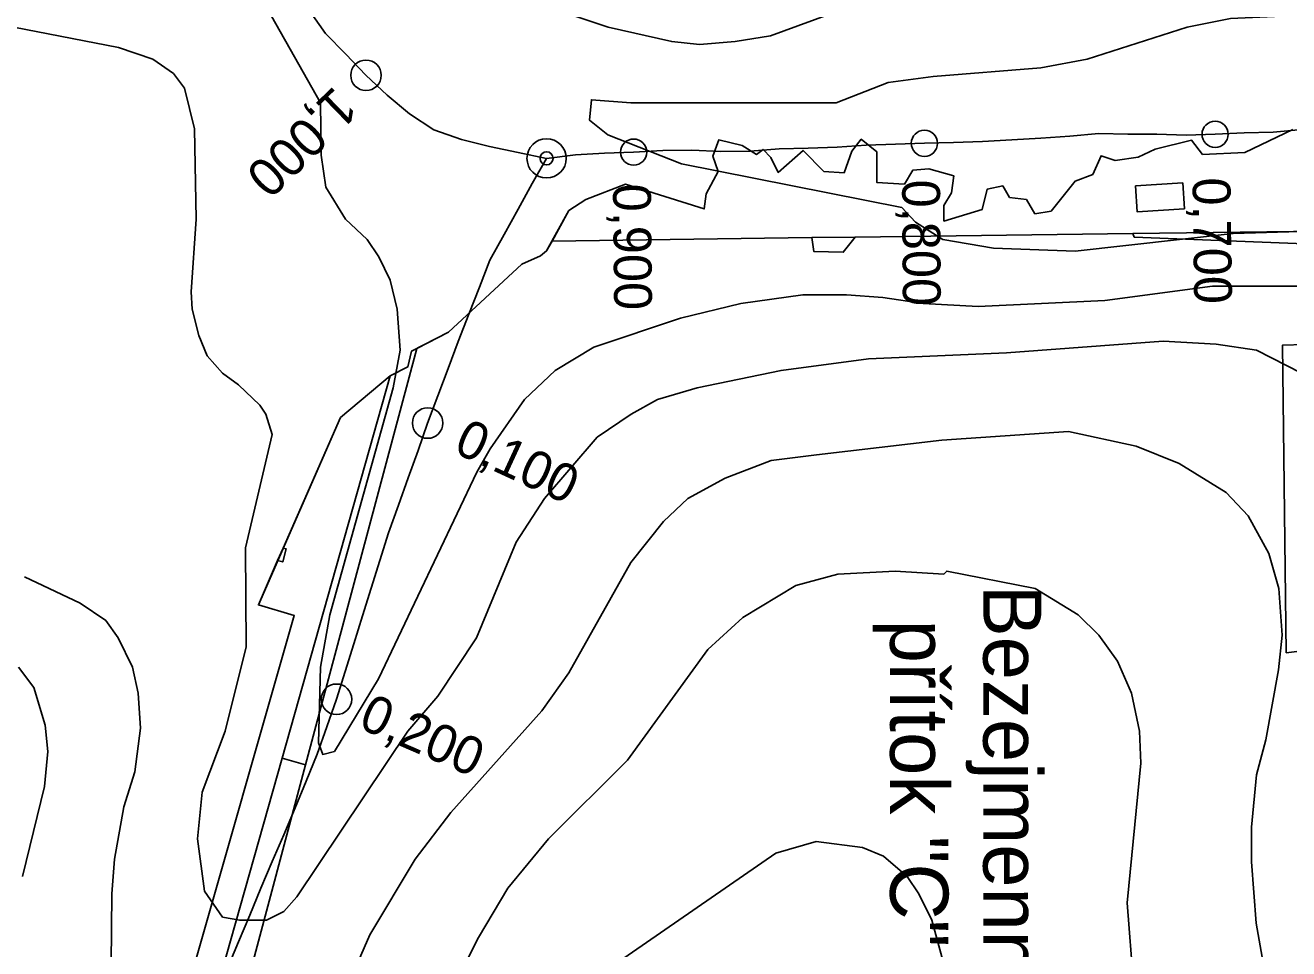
# Model space of a CAD drawing. Extents: x -510989 to -501240, y -1184665 to -1176098.
# Drawn here: x -505664.2 to -505230.1, y -1181158.8 to -1180841.4 of the extents above; entities that cross this region are included whole.
import ezdxf

# ---------------------------------------------------------------- set-up
doc = ezdxf.new("R2010")
doc.units = 0
for name, color, linetype in [('lesni_pozemek', 7, 'Continuous'), ('NAVRH_rozvodnice', 7, 'Continuous'), ('ostatni_plocha_x_jina_plocha', 7, 'Continuous'), ('ostatni_plocha_x_manipulacni_plocha', 7, 'Continuous'), ('popis', 7, 'Continuous'), ('trasovani_toku', 7, 'Continuous'), ('vrstevnice_01', 7, 'Continuous'), ('vrstevnice_02', 7, 'Continuous'), ('zahrada', 7, 'Continuous'), ('zastavena_plocha_a_nadvori', 7, 'Continuous')]:
    doc.layers.add(name, color=color, linetype=linetype)

msp = doc.modelspace()

# ---------------------------------------------------------------- linework, layer by layer
at = {"layer": 'lesni_pozemek'}
for points in [[(-505674.96, -1181355.48), (-505644.72, -1181306.04), (-505608, -1181246), (-505567.89, -1181095.59), (-505529.72, -1180952.45), (-505518.81, -1180946.9), (-505493.6, -1180923.5), (-505487.17, -1180920.65), (-505485.1, -1180918.93), (-505483.22, -1180915.53), (-505393.95, -1180914.37), (-505393.27, -1180919.16), (-505383.14, -1180919.37), (-505379.08, -1180914.18), (-505283.65, -1180912.95), (-505283.21, -1180914.2), (-505209.9, -1180917.09)], [(-505209.22, -1180950.61), (-505232.2, -1180951.3), (-505230.99, -1181057.06), (-505207.11, -1181054.09)]]:
    msp.add_lwpolyline(points, dxfattribs=at)
at = {"layer": 'ostatni_plocha_x_jina_plocha'}
for points in [[(-505529.72, -1180952.45), (-505567.89, -1181095.59), (-505575.96, -1181093.31), (-505538.83, -1180961.92), (-505532.82, -1180958.84), (-505531.48, -1180953.35)], [(-505574.53, -1181021.38), (-505575.76, -1181025.82), (-505577.49, -1181025.34), (-505575.64, -1181021.07)], [(-505575.96, -1181093.31), (-505567.89, -1181095.59), (-505608, -1181246), (-505644.72, -1181306.04), (-505617.63, -1181240.76)]]:
    msp.add_lwpolyline(points, close=True, dxfattribs=at)
msp.add_lwpolyline([(-505683.51, -1181360.81), (-505662.2, -1181330.12), (-505652.34, -1181315.5), (-505639.92, -1181290.41), (-505621.95, -1181246.92), (-505642.16, -1181237.85), (-505641, -1181236), (-505622.93, -1181170.52), (-505607.46, -1181169.03), (-505571.78, -1181044.28), (-505584.13, -1181040.64), (-505577.49, -1181025.34), (-505575.76, -1181025.82), (-505574.53, -1181021.38), (-505575.64, -1181021.07), (-505555.89, -1180976.24), (-505538.83, -1180961.92), (-505575.96, -1181093.31), (-505617.63, -1181240.76), (-505644.72, -1181306.04), (-505674.96, -1181355.48)], dxfattribs=at)
at = {"layer": 'ostatni_plocha_x_manipulacni_plocha'}
msp.add_lwpolyline([(-505210, -1180912), (-505283.65, -1180912.95), (-505379.08, -1180914.18), (-505393.95, -1180914.37), (-505483.22, -1180915.53), (-505477.44, -1180905.06), (-505471.56, -1180901.31), (-505457.98, -1180896.02), (-505430.94, -1180904.5), (-505430.28, -1180899.32), (-505426.13, -1180891.6), (-505427.93, -1180886.32), (-505425.95, -1180880.76), (-505417.88, -1180882.74), (-505412.95, -1180885.75), (-505410.73, -1180884.05), (-505408.09, -1180886.83), (-505405.5, -1180891.97), (-505396.96, -1180884.38), (-505389.82, -1180891.59), (-505382.89, -1180892.07), (-505380.17, -1180884.63), (-505376.96, -1180880.57), (-505371.68, -1180884.82), (-505371.59, -1180895.43), (-505362.16, -1180895.99), (-505359.28, -1180891.23), (-505353.77, -1180890.71), (-505345.23, -1180893.16), (-505345.94, -1180899.01), (-505348.65, -1180903.29), (-505348.6, -1180908.67), (-505335.45, -1180904.75), (-505333.75, -1180897.72), (-505328.37, -1180896.59), (-505326.02, -1180900.55), (-505320.23, -1180901.31), (-505317.31, -1180906.17), (-505311.75, -1180905.32), (-505303.5, -1180894.99), (-505297.45, -1180892.69), (-505294.58, -1180886.22), (-505289.71, -1180887.88), (-505281.79, -1180886.7), (-505275.99, -1180883.96), (-505263.55, -1180880.85), (-505259.73, -1180885.83), (-505245.25, -1180885.12), (-505228.75, -1180877.16)], dxfattribs=at)
for points in [[(-505282.74, -1180896.51), (-505282.2, -1180905.45), (-505265.98, -1180904.47), (-505266.52, -1180895.54)], [(-505393.95, -1180914.37), (-505379.08, -1180914.18), (-505383.14, -1180919.37), (-505393.27, -1180919.16)], [(-505283.65, -1180912.95), (-505210, -1180912), (-505209.9, -1180917.09), (-505283.21, -1180914.2)]]:
    msp.add_lwpolyline(points, close=True, dxfattribs=at)
at = {"layer": 'popis'}
msp.add_lwpolyline([(-505607.46, -1181169.03), (-505571.78, -1181044.28), (-505584.13, -1181040.64), (-505555.89, -1180976.24), (-505538.83, -1180961.92), (-505532.82, -1180958.84), (-505531.48, -1180953.35), (-505518.81, -1180946.9), (-505493.6, -1180923.5), (-505487.17, -1180920.65), (-505485.1, -1180918.93), (-505477.44, -1180905.06), (-505471.56, -1180901.31), (-505457.98, -1180896.02), (-505430.94, -1180904.5), (-505430.28, -1180899.32), (-505426.13, -1180891.6), (-505427.93, -1180886.32), (-505425.95, -1180880.76), (-505417.88, -1180882.74), (-505412.95, -1180885.75), (-505410.73, -1180884.05), (-505408.09, -1180886.83), (-505405.5, -1180891.97), (-505396.96, -1180884.38), (-505389.82, -1180891.59), (-505382.89, -1180892.07), (-505380.17, -1180884.63), (-505376.96, -1180880.57), (-505371.68, -1180884.82), (-505371.59, -1180895.43), (-505362.16, -1180895.99), (-505359.28, -1180891.23), (-505353.77, -1180890.71), (-505345.23, -1180893.16), (-505345.94, -1180899.01), (-505348.65, -1180903.29), (-505348.6, -1180908.67), (-505335.45, -1180904.75), (-505333.75, -1180897.72), (-505328.37, -1180896.59), (-505326.02, -1180900.55), (-505320.23, -1180901.31), (-505317.31, -1180906.17), (-505311.75, -1180905.32), (-505303.5, -1180894.99), (-505297.45, -1180892.69), (-505294.58, -1180886.22), (-505289.71, -1180887.88), (-505281.79, -1180886.7), (-505275.99, -1180883.96), (-505263.55, -1180880.85), (-505259.73, -1180885.83), (-505245.25, -1180885.12), (-505228.75, -1180877.16)], dxfattribs=at)
at = {"layer": 'trasovani_toku'}
for p, q in [((-505561.1, -1180844.25), (-505566.78, -1180836.02)), ((-505554.04, -1180851.33), (-505561.1, -1180844.25)), ((-505547.14, -1180858.57), (-505554.04, -1180851.33)), ((-505539.84, -1180865.41), (-505547.14, -1180858.57)), ((-505532.21, -1180871.87), (-505539.84, -1180865.41)), ((-505523.79, -1180877.27), (-505532.21, -1180871.87)), ((-505514.36, -1180880.59), (-505523.79, -1180877.27)), ((-505504.67, -1180883.04), (-505514.36, -1180880.59)), ((-505325.3, -1180880.76), (-505335.29, -1180881.31)), ((-505315.32, -1180880.17), (-505325.3, -1180880.76)), ((-505305.34, -1180879.49), (-505315.32, -1180880.17)), ((-505295.39, -1180878.52), (-505305.34, -1180879.49)), ((-505285.39, -1180878.81), (-505295.39, -1180878.52)), ((-505275.39, -1180878.82), (-505285.39, -1180878.81)), ((-505265.4, -1180879.14), (-505275.39, -1180878.82)), ((-505255.4, -1180878.85), (-505265.4, -1180879.14)), ((-505245.41, -1180878.38), (-505255.4, -1180878.85)), ((-505235.42, -1180878.16), (-505245.41, -1180878.38)), ((-505225.46, -1180877.2), (-505235.42, -1180878.16)), ((-505494.88, -1180885.08), (-505504.67, -1180883.04)), ((-505485.09, -1180887.12), (-505494.88, -1180885.08)), ((-505455.18, -1180884.98), (-505465.17, -1180885.32)), ((-505445.2, -1180884.42), (-505455.18, -1180884.98)), ((-505435.2, -1180884.35), (-505445.2, -1180884.42)), ((-505425.2, -1180884.73), (-505435.2, -1180884.35)), ((-505415.2, -1180884.59), (-505425.2, -1180884.73)), ((-505405.23, -1180883.83), (-505415.2, -1180884.59)), ((-505395.23, -1180883.66), (-505405.23, -1180883.83)), ((-505385.24, -1180883.23), (-505395.23, -1180883.66)), ((-505375.27, -1180882.58), (-505385.24, -1180883.23)), ((-505365.27, -1180882.2), (-505375.27, -1180882.58)), ((-505355.28, -1180881.94), (-505365.27, -1180882.2)), ((-505345.28, -1180881.64), (-505355.28, -1180881.94)), ((-505335.29, -1180881.31), (-505345.28, -1180881.64)), ((-505485.09, -1180887.12), (-505490.06, -1180895.79)), ((-505475.16, -1180885.94), (-505485.09, -1180887.12)), ((-505465.17, -1180885.32), (-505475.16, -1180885.94)), ((-505490.06, -1180895.79), (-505494.89, -1180904.55)), ((-505494.89, -1180904.55), (-505499.71, -1180913.31)), ((-505499.71, -1180913.31), (-505504.54, -1180922.07)), ((-505504.54, -1180922.07), (-505508.17, -1180931.39)), ((-505508.17, -1180931.39), (-505511.81, -1180940.7)), ((-505511.81, -1180940.7), (-505515.44, -1180950.02)), ((-505515.44, -1180950.02), (-505518.95, -1180959.38)), ((-505518.95, -1180959.38), (-505522.45, -1180968.75)), ((-505522.45, -1180968.75), (-505525.96, -1180978.11)), ((-505525.96, -1180978.11), (-505529.26, -1180987.55)), ((-505529.26, -1180987.55), (-505532.62, -1180996.97)), ((-505532.62, -1180996.97), (-505535.99, -1181006.39)), ((-505535.99, -1181006.39), (-505539.36, -1181015.8)), ((-505539.36, -1181015.8), (-505542.34, -1181025.35)), ((-505542.34, -1181025.35), (-505545.33, -1181034.89)), ((-505545.33, -1181034.89), (-505548.31, -1181044.43)), ((-505548.31, -1181044.43), (-505551.3, -1181053.98)), ((-505551.3, -1181053.98), (-505554.28, -1181063.52)), ((-505554.28, -1181063.52), (-505557.27, -1181073.07)), ((-505557.27, -1181073.07), (-505560.6, -1181082.49)), ((-505560.6, -1181082.49), (-505563.94, -1181091.92)), ((-505563.94, -1181091.92), (-505567.64, -1181101.21)), ((-505567.64, -1181101.21), (-505571.51, -1181110.43)), ((-505571.51, -1181110.43), (-505575.42, -1181119.64)), ((-505575.42, -1181119.64), (-505579.33, -1181128.84)), ((-505579.33, -1181128.84), (-505583.22, -1181138.05)), ((-505583.22, -1181138.05), (-505587.09, -1181147.27)), ((-505587.09, -1181147.27), (-505590.96, -1181156.5)), ((-505590.96, -1181156.5), (-505594.82, -1181165.72))]:
    msp.add_line(p, q, dxfattribs=at)
for centre, radius in [((-505547.14, -1180858.57), 5.25), ((-505255.4, -1180878.85), 4.5), ((-505485.09, -1180887.12), 6.75), ((-505455.18, -1180884.98), 4.5), ((-505355.28, -1180881.94), 4.5), ((-505485.09, -1180887.12), 2.25), ((-505525.96, -1180978.11), 5.25), ((-505557.27, -1181073.07), 5.25)]:
    msp.add_circle(centre, radius, dxfattribs=at)
at = {"layer": 'vrstevnice_01'}
for points in [[(-505207.41, -1180812), (-505243.31, -1180811), (-505258.81, -1180812), (-505273.59, -1180815), (-505296.19, -1180825), (-505314.31, -1180831), (-505338.09, -1180833), (-505363.69, -1180833), (-505383.41, -1180836), (-505408.19, -1180845), (-505420.31, -1180847), (-505432.5, -1180848), (-505442.09, -1180847), (-505463.91, -1180842), (-505511.91, -1180826), (-505534.91, -1180820), (-505558.91, -1180816), (-505580, -1180814), (-505588.41, -1180815), (-505587, -1180825), (-505562.81, -1180868)], [(-505562.81, -1180868), (-505562.5, -1180886), (-505560.91, -1180897), (-505554.19, -1180908), (-505546.69, -1180915), (-505542.69, -1180921), (-505538.81, -1180929), (-505536.41, -1180939), (-505535.41, -1180953), (-505537.81, -1180966), (-505559.59, -1181044), (-505562.81, -1181062), (-505563.5, -1181088), (-505562, -1181092), (-505558, -1181091), (-505542.81, -1181066), (-505509.09, -1180995), (-505504.5, -1180987), (-505492.69, -1180970), (-505482.09, -1180960), (-505468.81, -1180952), (-505439.09, -1180942), (-505418.31, -1180937), (-505397, -1180934), (-505382, -1180934), (-505369.59, -1180935), (-505355.69, -1180937), (-505336.81, -1180938), (-505293.31, -1180936), (-505256.31, -1180931), (-505221.31, -1180931)], [(-505557.19, -1181180), (-505545.81, -1181154), (-505530.19, -1181128), (-505518, -1181112), (-505486.69, -1181077), (-505477.41, -1181064), (-505456.19, -1181026), (-505444.91, -1181012), (-505436.59, -1181004), (-505423.69, -1180997), (-505407.91, -1180991), (-505392.41, -1180989), (-505349.31, -1180984), (-505305.81, -1180981), (-505282.5, -1180986), (-505267.81, -1180992), (-505251.59, -1181002), (-505244, -1181010), (-505237, -1181023), (-505233.5, -1181035), (-505232.41, -1181051), (-505233.59, -1181063), (-505238, -1181087), (-505241.19, -1181099), (-505242.91, -1181117), (-505242.91, -1181129), (-505241.31, -1181150), (-505234.41, -1181189)], [(-505664.5, -1181031), (-505645.31, -1181040), (-505636.5, -1181046), (-505632.31, -1181052), (-505627.31, -1181062), (-505625.41, -1181071), (-505624.59, -1181083), (-505626.59, -1181098), (-505630.31, -1181110), (-505633.59, -1181128), (-505634.5, -1181140), (-505634.81, -1181176), (-505636.69, -1181201), (-505646.91, -1181249), (-505650.81, -1181260), (-505655.59, -1181281), (-505656.59, -1181296), (-505654.5, -1181303), (-505651.69, -1181306), (-505645.5, -1181307), (-505639.41, -1181307), (-505638.19, -1181310), (-505639.43, -1181312.94)], [(-505346.5, -1181339.37), (-505349.19, -1181326), (-505351, -1181314), (-505352.31, -1181295), (-505351.09, -1181250), (-505343.81, -1181209), (-505343.31, -1181197), (-505345.69, -1181175), (-505352.69, -1181149), (-505357.19, -1181140), (-505361.19, -1181134), (-505369.31, -1181127), (-505376.59, -1181124), (-505392.5, -1181122), (-505406.31, -1181126), (-505473, -1181172), (-505491.81, -1181192), (-505509.91, -1181219), (-505517.59, -1181233), (-505523.31, -1181246), (-505531.19, -1181278), (-505535.5, -1181291), (-505546.09, -1181311), (-505552.23, -1181320.81)]]:
    msp.add_lwpolyline(points, dxfattribs=at)
at = {"layer": 'vrstevnice_02'}
for points in [[(-505218.59, -1180912), (-505249.19, -1180913), (-505303.5, -1180919), (-505331.5, -1180918), (-505349, -1180915), (-505358.31, -1180909), (-505363.09, -1180904), (-505438.69, -1180889), (-505464.09, -1180879), (-505470.31, -1180874), (-505469.69, -1180867), (-505456.19, -1180868), (-505385.59, -1180868), (-505367.69, -1180861), (-505352.31, -1180859), (-505315.31, -1180856), (-505299.31, -1180853), (-505265, -1180842), (-505250.09, -1180839), (-505227.41, -1180838)], [(-505225.69, -1180961), (-505241.19, -1180953), (-505255.09, -1180951), (-505273.31, -1180950), (-505327.09, -1180954), (-505374.5, -1180956), (-505404.5, -1180960), (-505433.41, -1180966), (-505447, -1180970), (-505456.09, -1180975), (-505467.69, -1180983), (-505485.81, -1181004), (-505495.59, -1181019), (-505509.19, -1181052), (-505522.5, -1181072), (-505532.81, -1181084), (-505570.91, -1181141), (-505575.41, -1181146), (-505581.31, -1181149), (-505590.5, -1181149), (-505596.41, -1181148), (-505602.59, -1181139), (-505605, -1181121), (-505603.41, -1181105), (-505595.5, -1181084), (-505588.31, -1181055), (-505588.5, -1181021), (-505579.41, -1180982), (-505581.59, -1180975), (-505583.59, -1180972), (-505591, -1180965), (-505596.41, -1180961), (-505601.69, -1180955), (-505604.59, -1180948), (-505606.81, -1180939), (-505607.19, -1180933), (-505605.5, -1180908), (-505606.09, -1180877), (-505609.5, -1180863), (-505613.31, -1180858), (-505620.41, -1180853), (-505632.19, -1180849), (-505668.19, -1180842)], [(-505533.69, -1181205), (-505508.5, -1181155), (-505498.41, -1181138), (-505484.41, -1181121), (-505457.31, -1181094), (-505429.69, -1181056), (-505417.69, -1181045), (-505399.41, -1181034), (-505385, -1181030), (-505365.31, -1181029), (-505348.59, -1181030), (-505347.59, -1181029), (-505317.19, -1181035), (-505302.41, -1181044), (-505295.31, -1181051), (-505289, -1181060), (-505284.09, -1181071), (-505281.41, -1181084), (-505280.91, -1181095), (-505285.59, -1181143), (-505283.5, -1181171)], [(-505665.19, -1181134), (-505657.59, -1181103), (-505656.41, -1181091), (-505657.41, -1181082), (-505661.31, -1181069), (-505666.5, -1181062)]]:
    msp.add_lwpolyline(points, dxfattribs=at)
at = {"layer": 'zahrada'}
msp.add_lwpolyline([(-505209.22, -1180950.61), (-505207.11, -1181054.09), (-505230.99, -1181057.06), (-505232.2, -1180951.3)], close=True, dxfattribs=at)
at = {"layer": 'zastavena_plocha_a_nadvori'}
msp.add_lwpolyline([(-505282.74, -1180896.51), (-505266.52, -1180895.54), (-505265.98, -1180904.47), (-505282.2, -1180905.45)], close=True, dxfattribs=at)

# ---------------------------------------------------------------- texts
at = {"layer": 'NAVRH_rozvodnice'}
for s, p in [('Bezejmenný', (-505335.06, -1181033.71)), ('přítok "C"', (-505367.06, -1181045.69))]:
    msp.add_text(s, height=20, rotation=270, dxfattribs=at).set_placement(p)
at = {"layer": 'trasovani_toku'}
for s, rotation, p in [('1,000', 224.1415, (-505557.98, -1180861.87)), ('0,900', 270.5679, (-505462.29, -1180895.86)), ('0,800', 270.3661, (-505362.95, -1180894.45)), ('0,700', 270.782, (-505263.17, -1180893.76)), ('0,100', 335.2301, (-505517.52, -1180988)), ('0,200', 336.5618, (-505550.23, -1181082.68))]:
    msp.add_text(s, height=13, rotation=rotation, dxfattribs=at).set_placement(p)

doc.saveas('drawing.dxf')
